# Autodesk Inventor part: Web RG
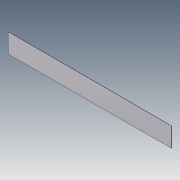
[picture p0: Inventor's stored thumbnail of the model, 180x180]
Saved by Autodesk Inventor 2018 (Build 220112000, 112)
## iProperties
Created: 2018-02
Part Number: Web RG
Material: Steel, Mild
Document SubType Name: Modeling
Designer: STK
Density: 7.85 g/cm^3
Appearance: Opal
Author: STK
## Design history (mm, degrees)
sketch "Sketch1"
  geometry: L1 (-457.2, 4.763)-(457.2, 4.763); L2 (457.2, 4.763)-(457.2, -4.762); L3 (457.2, -4.762)-(-457.2, -4.763); L4 (-457.2, -4.763)-(-457.2, 4.763); L5 (-457.2, 4.763)-(457.2, -4.762); L6 (457.2, 4.763)-(-457.2, -4.763); 1 further point
  constraints: 12 end point, 2 midpoint, 2 parallel, 1 horizontal, 1 perpendicular
  dimensions: "d0" = 9.525 distance of L1.end L2.end; "d1" = 914.4 distance of L1.start L1.end
extrude "Extrusion1" new body sketch "Sketch1" stored distance "d2" = 7747; taper "d3" = 0 deg
body "Solid1"
